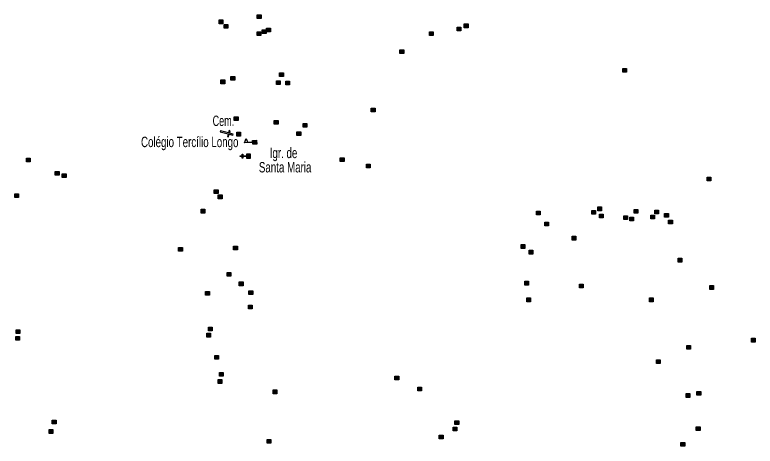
# Model space of a CAD drawing. Extents: x 649.2 to 674.4, y 7040 to 7068.1.
# Drawn here: x 655.33 to 661.02, y 7040.27 to 7043.58 of the extents above; entities that cross this region are included whole.
import ezdxf
from ezdxf.enums import TextEntityAlignment as Align

# ---------------------------------------------------------------- set-up
doc = ezdxf.new("R2010")
doc.units = 0
doc.header["$LTSCALE"] = 0.032
for name, color, linetype, lineweight in [('2', 7, 'Continuous', 25), ('20', 7, 'Continuous', 25), ('4', 7, 'Continuous', 25), ('6', 7, 'Continuous', 25)]:
    doc.layers.add(name, color=color, linetype=linetype, lineweight=lineweight)
doc.layers.add('61', color=7, linetype='Continuous')

msp = doc.modelspace()

# ---------------------------------------------------------------- hatches: boundary and pattern name
at = {"layer": '2'}
for points in [[(657.195, 7043.5846), (657.224, 7043.5846), (657.224, 7043.5556), (657.195, 7043.5556)], [(656.901, 7043.5452), (656.93, 7043.5452), (656.93, 7043.5162), (656.901, 7043.5162)], [(656.9398, 7043.5102), (656.9688, 7043.5102), (656.9688, 7043.4812), (656.9398, 7043.4812)], [(658.7861, 7043.5145), (658.8151, 7043.5145), (658.8151, 7043.4855), (658.7861, 7043.4855)], [(657.1931, 7043.4535), (657.2221, 7043.4535), (657.2221, 7043.4245), (657.1931, 7043.4245)], [(657.2332, 7043.4701), (657.2622, 7043.4701), (657.2622, 7043.4411), (657.2332, 7043.4411)], [(657.2663, 7043.4815), (657.2953, 7043.4815), (657.2953, 7043.4525), (657.2663, 7043.4525)], [(658.5183, 7043.4544), (658.5473, 7043.4544), (658.5473, 7043.4254), (658.5183, 7043.4254)], [(658.7311, 7043.4906), (658.7601, 7043.4906), (658.7601, 7043.4616), (658.7311, 7043.4616)], [(658.2917, 7043.3147), (658.3207, 7043.3147), (658.3207, 7043.2857), (658.2917, 7043.2857)], [(660.004, 7043.1727), (660.033, 7043.1727), (660.033, 7043.1437), (660.004, 7043.1437)], [(656.9924, 7043.1109), (657.0214, 7043.1109), (657.0214, 7043.0819), (656.9924, 7043.0819)], [(657.367, 7043.1391), (657.396, 7043.1391), (657.396, 7043.1101), (657.367, 7043.1101)], [(656.9154, 7043.0831), (656.9444, 7043.0831), (656.9444, 7043.0541), (656.9154, 7043.0541)], [(657.3415, 7043.0765), (657.3705, 7043.0765), (657.3705, 7043.0475), (657.3415, 7043.0475)], [(657.4145, 7043.0744), (657.4435, 7043.0744), (657.4435, 7043.0454), (657.4145, 7043.0454)], [(658.0717, 7042.8673), (658.1007, 7042.8673), (658.1007, 7042.8383), (658.0717, 7042.8383)], [(657.0177, 7042.7994), (657.0467, 7042.7994), (657.0467, 7042.7704), (657.0177, 7042.7704)], [(657.3253, 7042.7725), (657.3543, 7042.7725), (657.3543, 7042.7435), (657.3253, 7042.7435)], [(657.5473, 7042.7484), (657.5763, 7042.7484), (657.5763, 7042.7194), (657.5473, 7042.7194)], [(657.0375, 7042.681), (657.0665, 7042.681), (657.0665, 7042.652), (657.0375, 7042.652)], [(657.4995, 7042.6847), (657.5285, 7042.6847), (657.5285, 7042.6557), (657.4995, 7042.6557)], [(657.8328, 7042.4842), (657.8618, 7042.4842), (657.8618, 7042.4552), (657.8328, 7042.4552)], [(655.4197, 7042.4813), (655.4487, 7042.4813), (655.4487, 7042.4523), (655.4197, 7042.4523)], [(658.035, 7042.4354), (658.064, 7042.4354), (658.064, 7042.4064), (658.035, 7042.4064)], [(655.6416, 7042.3798), (655.6706, 7042.3798), (655.6706, 7042.3508), (655.6416, 7042.3508)], [(655.6959, 7042.3617), (655.7249, 7042.3617), (655.7249, 7042.3327), (655.6959, 7042.3327)], [(660.6536, 7042.3359), (660.6826, 7042.3359), (660.6826, 7042.3069), (660.6536, 7042.3069)], [(655.3308, 7042.2082), (655.3598, 7042.2082), (655.3598, 7042.1792), (655.3308, 7042.1792)], [(656.8646, 7042.2384), (656.8936, 7042.2384), (656.8936, 7042.2094), (656.8646, 7042.2094)], [(656.8947, 7042.1984), (656.9237, 7042.1984), (656.9237, 7042.1694), (656.8947, 7042.1694)], [(656.7631, 7042.0889), (656.7921, 7042.0889), (656.7921, 7042.0599), (656.7631, 7042.0599)], [(659.8119, 7042.1065), (659.8409, 7042.1065), (659.8409, 7042.0775), (659.8119, 7042.0775)], [(660.0926, 7042.0872), (660.1216, 7042.0872), (660.1216, 7042.0582), (660.0926, 7042.0582)], [(659.3414, 7042.0744), (659.3704, 7042.0744), (659.3704, 7042.0454), (659.3414, 7042.0454)], [(659.7665, 7042.0789), (659.7955, 7042.0789), (659.7955, 7042.0499), (659.7665, 7042.0499)], [(659.8263, 7042.0512), (659.8553, 7042.0512), (659.8553, 7042.0222), (659.8263, 7042.0222)], [(660.0129, 7042.0386), (660.0419, 7042.0386), (660.0419, 7042.0096), (660.0129, 7042.0096)], [(660.2201, 7042.043), (660.2491, 7042.043), (660.2491, 7042.014), (660.2201, 7042.014)], [(660.2505, 7042.0814), (660.2795, 7042.0814), (660.2795, 7042.0524), (660.2505, 7042.0524)], [(660.3266, 7042.056), (660.3556, 7042.056), (660.3556, 7042.027), (660.3266, 7042.027)], [(659.4056, 7041.9903), (659.4346, 7041.9903), (659.4346, 7041.9613), (659.4056, 7041.9613)], [(660.0586, 7042.0278), (660.0876, 7042.0278), (660.0876, 7041.9988), (660.0586, 7041.9988)], [(660.357, 7042.0046), (660.386, 7042.0046), (660.386, 7041.9756), (660.357, 7041.9756)], [(659.616, 7041.8807), (659.645, 7041.8807), (659.645, 7041.8517), (659.616, 7041.8517)], [(657.0126, 7041.805), (657.0416, 7041.805), (657.0416, 7041.776), (657.0126, 7041.776)], [(659.223, 7041.8165), (659.252, 7041.8165), (659.252, 7041.7875), (659.223, 7041.7875)], [(656.5901, 7041.7949), (656.6191, 7041.7949), (656.6191, 7041.7659), (656.5901, 7041.7659)], [(659.2839, 7041.7734), (659.3129, 7041.7734), (659.3129, 7041.7444), (659.2839, 7041.7444)], [(660.4307, 7041.7112), (660.4597, 7041.7112), (660.4597, 7041.6822), (660.4307, 7041.6822)], [(656.9633, 7041.6033), (656.9923, 7041.6033), (656.9923, 7041.5743), (656.9633, 7041.5743)], [(657.0568, 7041.5292), (657.0858, 7041.5292), (657.0858, 7041.5002), (657.0568, 7041.5002)], [(659.2514, 7041.5349), (659.2804, 7041.5349), (659.2804, 7041.5059), (659.2514, 7041.5059)], [(657.1308, 7041.4612), (657.1598, 7041.4612), (657.1598, 7041.4322), (657.1308, 7041.4322)], [(659.6722, 7041.5124), (659.7012, 7041.5124), (659.7012, 7041.4834), (659.6722, 7041.4834)], [(660.6735, 7041.5017), (660.7025, 7041.5017), (660.7025, 7041.4727), (660.6735, 7041.4727)], [(656.7981, 7041.4563), (656.8271, 7041.4563), (656.8271, 7041.4273), (656.7981, 7041.4273)], [(659.2676, 7041.4065), (659.2966, 7041.4065), (659.2966, 7041.3775), (659.2676, 7041.3775)], [(660.2106, 7041.4061), (660.2396, 7041.4061), (660.2396, 7041.3771), (660.2106, 7041.3771)], [(657.1272, 7041.3519), (657.1562, 7041.3519), (657.1562, 7041.3229), (657.1272, 7041.3229)], [(656.82, 7041.1819), (656.849, 7041.1819), (656.849, 7041.1529), (656.82, 7041.1529)], [(655.3412, 7041.1622), (655.3702, 7041.1622), (655.3702, 7041.1332), (655.3412, 7041.1332)], [(656.8066, 7041.1345), (656.8356, 7041.1345), (656.8356, 7041.1055), (656.8066, 7041.1055)], [(655.3378, 7041.1097), (655.3668, 7041.1097), (655.3668, 7041.0807), (655.3378, 7041.0807)], [(660.9938, 7041.0965), (661.0228, 7041.0965), (661.0228, 7041.0675), (660.9938, 7041.0675)], [(660.496, 7041.0403), (660.525, 7041.0403), (660.525, 7041.0113), (660.496, 7041.0113)], [(656.8688, 7040.9648), (656.8978, 7040.9648), (656.8978, 7040.9358), (656.8688, 7040.9358)], [(660.2641, 7040.9307), (660.2931, 7040.9307), (660.2931, 7040.9017), (660.2641, 7040.9017)], [(656.8937, 7040.7783), (656.9227, 7040.7783), (656.9227, 7040.7493), (656.8937, 7040.7493)], [(656.9049, 7040.833), (656.9339, 7040.833), (656.9339, 7040.804), (656.9049, 7040.804)], [(658.2534, 7040.8052), (658.2824, 7040.8052), (658.2824, 7040.7762), (658.2534, 7040.7762)], [(658.429, 7040.7208), (658.458, 7040.7208), (658.458, 7040.6918), (658.429, 7040.6918)], [(657.3165, 7040.6987), (657.3455, 7040.6987), (657.3455, 7040.6697), (657.3165, 7040.6697)], [(660.4924, 7040.6709), (660.5214, 7040.6709), (660.5214, 7040.6419), (660.4924, 7040.6419)], [(660.5751, 7040.6867), (660.6041, 7040.6867), (660.6041, 7040.6577), (660.5751, 7040.6577)], [(655.619, 7040.4674), (655.648, 7040.4674), (655.648, 7040.4384), (655.619, 7040.4384)], [(658.7148, 7040.4608), (658.7438, 7040.4608), (658.7438, 7040.4318), (658.7148, 7040.4318)], [(655.5943, 7040.3939), (655.6233, 7040.3939), (655.6233, 7040.3649), (655.5943, 7040.3649)], [(658.7012, 7040.4132), (658.7302, 7040.4132), (658.7302, 7040.3842), (658.7012, 7040.3842)], [(660.5697, 7040.415), (660.5987, 7040.415), (660.5987, 7040.386), (660.5697, 7040.386)], [(658.5937, 7040.3506), (658.6227, 7040.3506), (658.6227, 7040.3216), (658.5937, 7040.3216)], [(657.27, 7040.3179), (657.299, 7040.3179), (657.299, 7040.2889), (657.27, 7040.2889)], [(660.4519, 7040.295), (660.4809, 7040.295), (660.4809, 7040.266), (660.4519, 7040.266)]]:
    msp.add_hatch(color=256, dxfattribs=at).paths.add_polyline_path(points)
at = {"layer": '4'}
msp.add_hatch(color=256, dxfattribs=at).paths.add_polyline_path([(657.1902, 7042.59), (657.1603, 7042.5887), (657.159, 7042.6187), (657.1889, 7042.6199)])
at = {"layer": '6'}
for points in [[(657.1122, 7042.4997), (657.1122, 7042.4947), (657.0847, 7042.4946), (657.0848, 7042.4821), (657.0798, 7042.4821), (657.0797, 7042.4946), (657.0622, 7042.4945), (657.0622, 7042.4995), (657.0797, 7042.4996), (657.0796, 7042.5121), (657.0846, 7042.5121), (657.0847, 7042.4996)], [(657.1123, 7042.4822), (657.1423, 7042.4824), (657.1421, 7042.5124), (657.1121, 7042.5122)]]:
    msp.add_hatch(color=256, dxfattribs=at).paths.add_polyline_path(points)

# ---------------------------------------------------------------- linework, layer by layer
at = {"layer": '2'}
for points in [[(657.195, 7043.5846), (657.224, 7043.5846), (657.224, 7043.5556), (657.195, 7043.5556)], [(656.901, 7043.5452), (656.93, 7043.5452), (656.93, 7043.5162), (656.901, 7043.5162)], [(656.9398, 7043.5102), (656.9688, 7043.5102), (656.9688, 7043.4812), (656.9398, 7043.4812)], [(658.7861, 7043.5145), (658.8151, 7043.5145), (658.8151, 7043.4855), (658.7861, 7043.4855)], [(657.1931, 7043.4535), (657.2221, 7043.4535), (657.2221, 7043.4245), (657.1931, 7043.4245)], [(657.2332, 7043.4701), (657.2622, 7043.4701), (657.2622, 7043.4411), (657.2332, 7043.4411)], [(657.2663, 7043.4815), (657.2953, 7043.4815), (657.2953, 7043.4525), (657.2663, 7043.4525)], [(658.5183, 7043.4544), (658.5473, 7043.4544), (658.5473, 7043.4254), (658.5183, 7043.4254)], [(658.7311, 7043.4906), (658.7601, 7043.4906), (658.7601, 7043.4616), (658.7311, 7043.4616)], [(658.2917, 7043.3147), (658.3207, 7043.3147), (658.3207, 7043.2857), (658.2917, 7043.2857)], [(660.004, 7043.1727), (660.033, 7043.1727), (660.033, 7043.1437), (660.004, 7043.1437)], [(656.9924, 7043.1109), (657.0214, 7043.1109), (657.0214, 7043.0819), (656.9924, 7043.0819)], [(657.367, 7043.1391), (657.396, 7043.1391), (657.396, 7043.1101), (657.367, 7043.1101)], [(656.9154, 7043.0831), (656.9444, 7043.0831), (656.9444, 7043.0541), (656.9154, 7043.0541)], [(657.3415, 7043.0765), (657.3705, 7043.0765), (657.3705, 7043.0475), (657.3415, 7043.0475)], [(657.4145, 7043.0744), (657.4435, 7043.0744), (657.4435, 7043.0454), (657.4145, 7043.0454)], [(658.0717, 7042.8673), (658.1007, 7042.8673), (658.1007, 7042.8383), (658.0717, 7042.8383)], [(657.0177, 7042.7994), (657.0467, 7042.7994), (657.0467, 7042.7704), (657.0177, 7042.7704)], [(657.3253, 7042.7725), (657.3543, 7042.7725), (657.3543, 7042.7435), (657.3253, 7042.7435)], [(657.5473, 7042.7484), (657.5763, 7042.7484), (657.5763, 7042.7194), (657.5473, 7042.7194)], [(657.0375, 7042.681), (657.0665, 7042.681), (657.0665, 7042.652), (657.0375, 7042.652)], [(657.4995, 7042.6847), (657.5285, 7042.6847), (657.5285, 7042.6557), (657.4995, 7042.6557)], [(657.8328, 7042.4842), (657.8618, 7042.4842), (657.8618, 7042.4552), (657.8328, 7042.4552)], [(655.4197, 7042.4813), (655.4487, 7042.4813), (655.4487, 7042.4523), (655.4197, 7042.4523)], [(658.035, 7042.4354), (658.064, 7042.4354), (658.064, 7042.4064), (658.035, 7042.4064)], [(655.6416, 7042.3798), (655.6706, 7042.3798), (655.6706, 7042.3508), (655.6416, 7042.3508)], [(655.6959, 7042.3617), (655.7249, 7042.3617), (655.7249, 7042.3327), (655.6959, 7042.3327)], [(660.6536, 7042.3359), (660.6826, 7042.3359), (660.6826, 7042.3069), (660.6536, 7042.3069)], [(655.3308, 7042.2082), (655.3598, 7042.2082), (655.3598, 7042.1792), (655.3308, 7042.1792)], [(656.8646, 7042.2384), (656.8936, 7042.2384), (656.8936, 7042.2094), (656.8646, 7042.2094)], [(656.8947, 7042.1984), (656.9237, 7042.1984), (656.9237, 7042.1694), (656.8947, 7042.1694)], [(656.7631, 7042.0889), (656.7921, 7042.0889), (656.7921, 7042.0599), (656.7631, 7042.0599)], [(659.8119, 7042.1065), (659.8409, 7042.1065), (659.8409, 7042.0775), (659.8119, 7042.0775)], [(660.0926, 7042.0872), (660.1216, 7042.0872), (660.1216, 7042.0582), (660.0926, 7042.0582)], [(659.3414, 7042.0744), (659.3704, 7042.0744), (659.3704, 7042.0454), (659.3414, 7042.0454)], [(659.7665, 7042.0789), (659.7955, 7042.0789), (659.7955, 7042.0499), (659.7665, 7042.0499)], [(659.8263, 7042.0512), (659.8553, 7042.0512), (659.8553, 7042.0222), (659.8263, 7042.0222)], [(660.0129, 7042.0386), (660.0419, 7042.0386), (660.0419, 7042.0096), (660.0129, 7042.0096)], [(660.2201, 7042.043), (660.2491, 7042.043), (660.2491, 7042.014), (660.2201, 7042.014)], [(660.2505, 7042.0814), (660.2795, 7042.0814), (660.2795, 7042.0524), (660.2505, 7042.0524)], [(660.3266, 7042.056), (660.3556, 7042.056), (660.3556, 7042.027), (660.3266, 7042.027)], [(659.4056, 7041.9903), (659.4346, 7041.9903), (659.4346, 7041.9613), (659.4056, 7041.9613)], [(660.0586, 7042.0278), (660.0876, 7042.0278), (660.0876, 7041.9988), (660.0586, 7041.9988)], [(660.357, 7042.0046), (660.386, 7042.0046), (660.386, 7041.9756), (660.357, 7041.9756)], [(659.616, 7041.8807), (659.645, 7041.8807), (659.645, 7041.8517), (659.616, 7041.8517)], [(657.0126, 7041.805), (657.0416, 7041.805), (657.0416, 7041.776), (657.0126, 7041.776)], [(659.223, 7041.8165), (659.252, 7041.8165), (659.252, 7041.7875), (659.223, 7041.7875)], [(656.5901, 7041.7949), (656.6191, 7041.7949), (656.6191, 7041.7659), (656.5901, 7041.7659)], [(659.2839, 7041.7734), (659.3129, 7041.7734), (659.3129, 7041.7444), (659.2839, 7041.7444)], [(660.4307, 7041.7112), (660.4597, 7041.7112), (660.4597, 7041.6822), (660.4307, 7041.6822)], [(656.9633, 7041.6033), (656.9923, 7041.6033), (656.9923, 7041.5743), (656.9633, 7041.5743)], [(657.0568, 7041.5292), (657.0858, 7041.5292), (657.0858, 7041.5002), (657.0568, 7041.5002)], [(659.2514, 7041.5349), (659.2804, 7041.5349), (659.2804, 7041.5059), (659.2514, 7041.5059)], [(657.1308, 7041.4612), (657.1598, 7041.4612), (657.1598, 7041.4322), (657.1308, 7041.4322)], [(659.6722, 7041.5124), (659.7012, 7041.5124), (659.7012, 7041.4834), (659.6722, 7041.4834)], [(660.6735, 7041.5017), (660.7025, 7041.5017), (660.7025, 7041.4727), (660.6735, 7041.4727)], [(656.7981, 7041.4563), (656.8271, 7041.4563), (656.8271, 7041.4273), (656.7981, 7041.4273)], [(659.2676, 7041.4065), (659.2966, 7041.4065), (659.2966, 7041.3775), (659.2676, 7041.3775)], [(660.2106, 7041.4061), (660.2396, 7041.4061), (660.2396, 7041.3771), (660.2106, 7041.3771)], [(657.1272, 7041.3519), (657.1562, 7041.3519), (657.1562, 7041.3229), (657.1272, 7041.3229)], [(656.82, 7041.1819), (656.849, 7041.1819), (656.849, 7041.1529), (656.82, 7041.1529)], [(655.3412, 7041.1622), (655.3702, 7041.1622), (655.3702, 7041.1332), (655.3412, 7041.1332)], [(656.8066, 7041.1345), (656.8356, 7041.1345), (656.8356, 7041.1055), (656.8066, 7041.1055)], [(655.3378, 7041.1097), (655.3668, 7041.1097), (655.3668, 7041.0807), (655.3378, 7041.0807)], [(660.9938, 7041.0965), (661.0228, 7041.0965), (661.0228, 7041.0675), (660.9938, 7041.0675)], [(660.496, 7041.0403), (660.525, 7041.0403), (660.525, 7041.0113), (660.496, 7041.0113)], [(656.8688, 7040.9648), (656.8978, 7040.9648), (656.8978, 7040.9358), (656.8688, 7040.9358)], [(660.2641, 7040.9307), (660.2931, 7040.9307), (660.2931, 7040.9017), (660.2641, 7040.9017)], [(656.8937, 7040.7783), (656.9227, 7040.7783), (656.9227, 7040.7493), (656.8937, 7040.7493)], [(656.9049, 7040.833), (656.9339, 7040.833), (656.9339, 7040.804), (656.9049, 7040.804)], [(658.2534, 7040.8052), (658.2824, 7040.8052), (658.2824, 7040.7762), (658.2534, 7040.7762)], [(658.429, 7040.7208), (658.458, 7040.7208), (658.458, 7040.6918), (658.429, 7040.6918)], [(657.3165, 7040.6987), (657.3455, 7040.6987), (657.3455, 7040.6697), (657.3165, 7040.6697)], [(660.4924, 7040.6709), (660.5214, 7040.6709), (660.5214, 7040.6419), (660.4924, 7040.6419)], [(660.5751, 7040.6867), (660.6041, 7040.6867), (660.6041, 7040.6577), (660.5751, 7040.6577)], [(655.619, 7040.4674), (655.648, 7040.4674), (655.648, 7040.4384), (655.619, 7040.4384)], [(658.7148, 7040.4608), (658.7438, 7040.4608), (658.7438, 7040.4318), (658.7148, 7040.4318)], [(655.5943, 7040.3939), (655.6233, 7040.3939), (655.6233, 7040.3649), (655.5943, 7040.3649)], [(658.7012, 7040.4132), (658.7302, 7040.4132), (658.7302, 7040.3842), (658.7012, 7040.3842)], [(660.5697, 7040.415), (660.5987, 7040.415), (660.5987, 7040.386), (660.5697, 7040.386)], [(658.5937, 7040.3506), (658.6227, 7040.3506), (658.6227, 7040.3216), (658.5937, 7040.3216)], [(657.27, 7040.3179), (657.299, 7040.3179), (657.299, 7040.2889), (657.27, 7040.2889)], [(660.4519, 7040.295), (660.4809, 7040.295), (660.4809, 7040.266), (660.4519, 7040.266)]]:
    msp.add_lwpolyline(points, close=True, dxfattribs=at)
at = {"layer": '20'}
for points in [[(656.9117, 7042.6914), (656.9098, 7042.6836), (656.9714, 7042.6681)], [(656.9816, 7042.6738), (656.9864, 7042.6932), (656.9782, 7042.6952), (656.9733, 7042.6758), (656.9117, 7042.6914)], [(656.9714, 7042.6681), (656.9665, 7042.6487), (656.9747, 7042.6466), (656.9796, 7042.666)], [(656.9796, 7042.666), (657.0067, 7042.6592), (657.0087, 7042.6669), (656.9816, 7042.6738)]]:
    msp.add_lwpolyline(points, dxfattribs=at)
at = {"layer": '4'}
msp.add_line((657.1597, 7042.6012), (657.1595, 7042.6062), dxfattribs=at)
for points in [[(657.1597, 7042.6012), (657.0973, 7042.5985), (657.1083, 7042.634), (657.12, 7042.6045), (657.1595, 7042.6062)], [(657.1902, 7042.59), (657.1603, 7042.5887), (657.159, 7042.6187), (657.1889, 7042.6199)]]:
    msp.add_lwpolyline(points, close=True, dxfattribs=at)
at = {"layer": '6'}
for points in [[(657.1122, 7042.4997), (657.1122, 7042.4947), (657.0847, 7042.4946), (657.0848, 7042.4821), (657.0798, 7042.4821), (657.0797, 7042.4946), (657.0622, 7042.4945), (657.0622, 7042.4995), (657.0797, 7042.4996), (657.0796, 7042.5121), (657.0846, 7042.5121), (657.0847, 7042.4996)], [(657.1123, 7042.4822), (657.1423, 7042.4824), (657.1421, 7042.5124), (657.1121, 7042.5122)]]:
    msp.add_lwpolyline(points, close=True, dxfattribs=at)

# ---------------------------------------------------------------- texts
at = {"layer": '61'}
for s, width, p in [('Cem.', 0.65, (657.0176, 7042.7291)), ('Colégio Tercílio Longo', 0.7, (657.0502, 7042.5666))]:
    msp.add_text(s, height=0.08, dxfattribs=dict(at, width=width)).set_placement(p, align=Align.RIGHT)
at = {"layer": '61', "width": 0.7}
for s, p in [('    Igr. de', (657.2073, 7042.4821)), ('Santa Maria', (657.2073, 7042.3721))]:
    msp.add_text(s, height=0.08, dxfattribs=at).set_placement(p)

doc.saveas('drawing.dxf')
